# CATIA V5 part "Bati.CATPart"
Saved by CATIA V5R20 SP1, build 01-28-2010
Part number: Bati
Bounding box of the stored display mesh (mm): x -70 to 70, y -20 to 15, z 0 to 75.099
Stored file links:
  E:\EDELI\gcausse\Edeli_2012_190_gcausse\Bati.CATPart
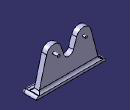
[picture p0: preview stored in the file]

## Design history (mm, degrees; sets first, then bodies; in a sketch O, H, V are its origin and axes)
Body1 (main body)
  Sketch1 on xy-plane, origin (0, 0, 0), H (1, 0, 0), V (0, 1, 0)
    line L1 (-70, 20) -> (70, 20)
    line L2 (70, 20) -> (70, -20)
    line L3 (70, -20) -> (-70, -20)
    line L4 (-70, -20) -> (-70, 20)
    horizontal: L1 H, L3 H
    vertical: L2 V, L4 V
  Pad1: profile Sketch1, direction (0, 0, 1), length 5
  Fillet1: radius 5, on edge [face of Pad1 from Sketch1.L4 | face of Pad1 from Sketch1.L1]; edge [face of Pad1 from Sketch1.L1 | face of Pad1 from Sketch1.L2]; edge [face of Pad1 from Sketch1.L2 | face of Pad1 from Sketch1.L3]; edge [face of Pad1 from Sketch1.L3 | face of Pad1 from Sketch1.L4]
  Sketch2 on end face of Pad1, origin (0, 0, 5), H (1, 0, 0), V (0, 1, 0)
    line L1 (-60, 5) -> (60, 5)
    line L2 (60, 5) -> (60, -5)
    line L3 (60, -5) -> (-60, -5)
    line L4 (-60, -5) -> (-60, 5)
    reference projected line E1 (-70, -20) -> (70, -20) from edge [face of Pad1 from Sketch1.L3 | end face of Pad1]
    reference projected line E2 (70, 20) -> (-70, 20) from edge [face of Pad1 from Sketch1.L1 | end face of Pad1]
    reference projected line E3 (70, -20) -> (70, 20) from edge [face of Pad1 from Sketch1.L2 | end face of Pad1]
    distance L1 E1 = 25
    distance L3 E2 = 25
    length L3 = 120
    distance L2 E3 = 10
    horizontal: L1 H, L3 H
    vertical: L2 V, L4 V
  Pad2: profile Sketch2, direction (0, 0, 1), length 80
  Sketch3 on face of Pad2 from Sketch2.L1, origin (0, 5, 0), H (-1, 0, 0), V (0, 0, 1)
    line L1 (-60, 5) -> (-44.5068, 63.9214)
    point P1 (-60, 5)
    line L2 (-15.7697, 64.8502) -> (-5.7697, 34.8502)
    line L3 (-5.7697, 34.8502) -> (5.8053, 34.8502)
    line L4 (5.8053, 34.8502) -> (15.7698, 64.7434)
    line L5 (44.5052, 63.821) -> (60, 5)
    point P8 (60, 5)
    arc A1 centre (30, 60) radius 15 from (44.5052, 63.821) to (15.7698, 64.7434) ccw
    point P9 (30, 60)
    arc A2 centre (-29.9999, 60.1068) radius 15 from (-15.7697, 64.8502) to (-44.5068, 63.9214) ccw
    point P10 (-29.9999, 60.1068)
    line L6 (60, 5) -> (60, 95)
    line L7 (60, 95) -> (-60, 95)
    line L8 (-60, 95) -> (-60, 5)
    reference projected point E1 (60, 5) from vertex [face of Pad2 from Sketch2.L1 | end face of Pad1 | face of Pad2 from Sketch2.L4]
    reference projected point E2 (-60, 5) from vertex [face of Pad2 from Sketch2.L2 | end face of Pad1 | face of Pad2 from Sketch2.L1]
    reference projected line E3 (-60, 85) -> (60, 85) from edge [face of Pad2 from Sketch2.L1 | end face of Pad2]
    radius A2 = 15
    radius A1 = 15
    length L2 = 31.6228
    length L4 = 31.5102
    angle L3 L2 = 71.5651
    angle L3 L4 = 71.565
    distance P10 P9 = 60
    distance P9 L6 = 30
    distance P9 E3 = 25
    horizontal: L3 H
    vertical: L6 V
    coincidence: P8 E1, P1 E2
    tangency: A2 L2, L1 A2, A1 L5, A1 L4
  Pocket1: profile Sketch3, direction (0, -1, 0), length 80
  Sketch4 on face of Pad2 from Sketch2.L1, origin (0, 5, 0), H (-1, 0, 0), V (0, 0, 1)
    circle A1 centre (-29.9999, 60.1068) radius 2.5
    point P2 (-32.557, 60.5306)
    circle A2 centre (30, 60) radius 2.5
    reference projected arc E1 centre (30, 60) radius 15 from (44.9997, 60.0894) to (15.0003, 59.9106) ccw from edge [face of Pad2 from Sketch2.L1 | face of Pocket1 from Sketch3.A1]
    reference projected arc E2 centre (-29.9999, 60.1068) radius 15 from (-14.9999, 60.1068) to (-44.9999, 60.1068) ccw from edge [face of Pad2 from Sketch2.L1 | face of Pocket1 from Sketch3.A2]
    radius A1 = 2.5
    radius A2 = 2.5
    concentricity: A2 E1, A1 E2
  Pad3: profile Sketch4, direction (0, 1, 0), length 5
  Fillet2: radius 5, on end face of Pad1
  Fillet3: radius 10, on edge [face of Pocket1 from Sketch3.L4 | face of Pocket1 from Sketch3.L3]; edge [face of Pocket1 from Sketch3.L3 | face of Pocket1 from Sketch3.L2]
  Sketch5 on end face of Pad3, origin (0, 10, 0), H (-1, 0, 0), V (0, 0, 1)
    circle A1 centre (-29.9999, 60.1068) radius 2.5
    reference projected circle E1 centre (-29.9999, 60.1068) radius 2.5 from edge [face of Pad3 from Sketch4.A1 | end face of Pad3]
    radius A1 = 2.5
    concentricity: A1 E1
  Pad4: profile Sketch5, direction (0, 1, 0), length 5
  Sketch6 on end face of Pad1, origin (0, 0, 5), H (1, 0, 0), V (0, 1, 0)
    line L1 (70, 10) -> (-70, 10)
    line L2 (-70, 10) -> (-70, 40)
    line L3 (-70, 40) -> (70, 40)
    line L4 (70, 40) -> (70, 10)
    horizontal: L1 H, L3 H
    vertical: L2 V, L4 V
  Pocket2: profile Sketch6, direction (0, 0, -1), length 5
